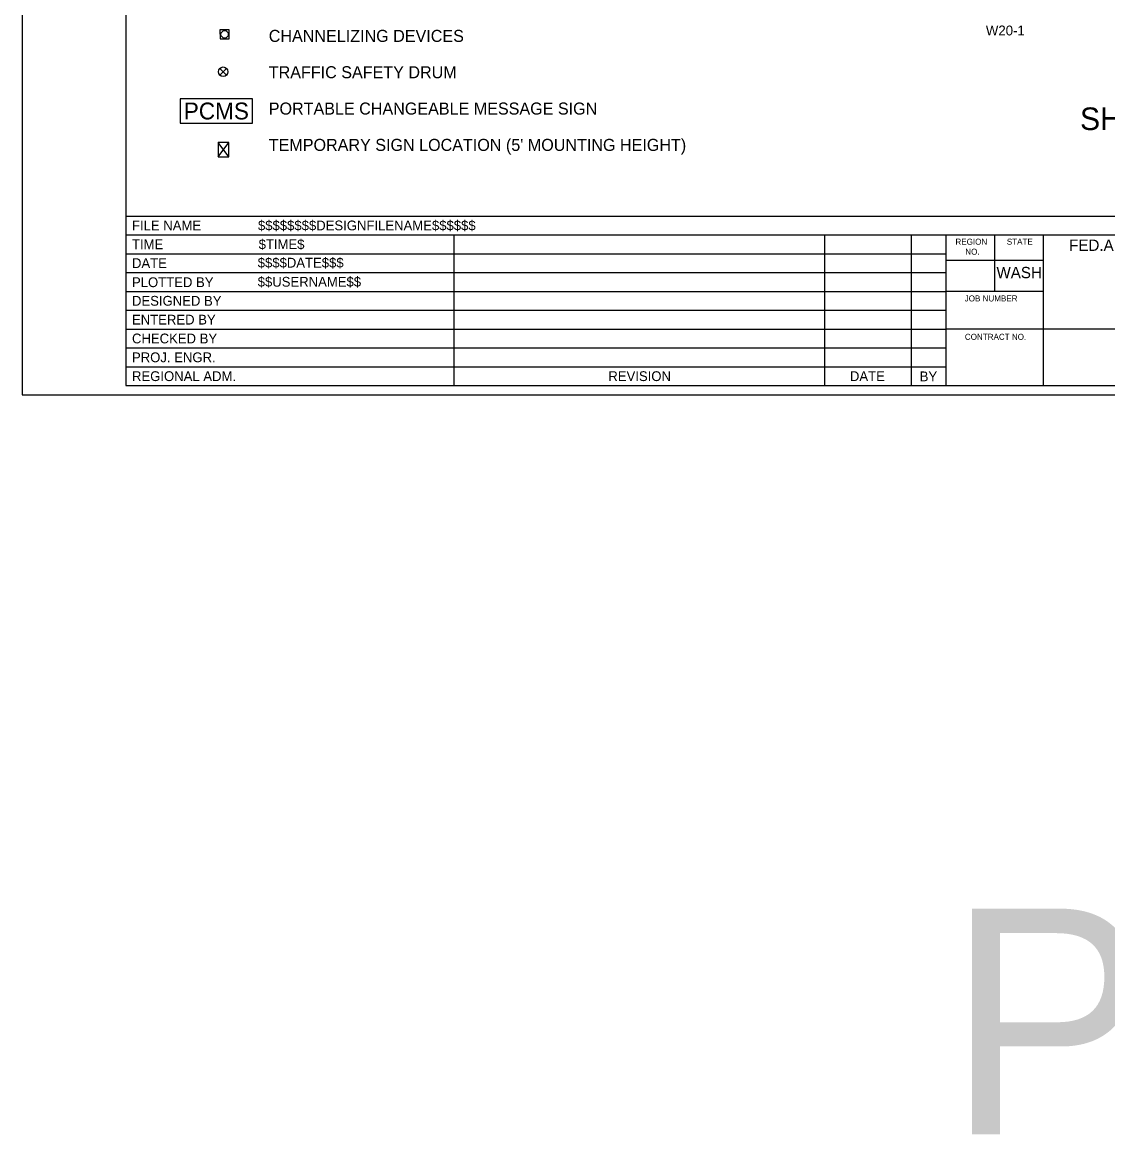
# Model space of a CAD drawing. Extents: x 99988 to 100172, y 99995 to 100047.
# Drawn here: x 99999.31 to 100006.52, y 99995.01 to 100002.41 of the extents above; entities that cross this region are included whole.
import ezdxf

# ---------------------------------------------------------------- set-up
doc = ezdxf.new("R2010")
doc.units = 0
for name, color, linetype in [('Default', 7, 'Continuous'), ('SH_DE_DetailBody1Text', 7, 'Continuous'), ('SH_DE_DetailHeading1Text', 7, 'Continuous'), ('SH_GI_PlotLimits', 7, 'Continuous'), ('SH_GI_SheetBorder', 7, 'Continuous'), ('SH_GI_SheetLocationText', 7, 'Continuous'), ('SH_GI_SheetTextInCells', 7, 'Continuous'), ('SH_GI_TitleBlockText', 7, 'Continuous'), ('TR_SN_WarningSigns', 7, 'Continuous'), ('TR_WZ_PortableChangeMessageSign', 7, 'Continuous'), ('TR_WZ_TrafficSafetyCone', 7, 'Continuous')]:
    doc.layers.add(name, color=color, linetype=linetype)

msp = doc.modelspace()

# ---------------------------------------------------------------- linework, layer by layer
at = {"layer": 'Default'}
for p, q in [((100000.6691, 100002.0611), (100000.6239, 100002.1064)), ((100000.6691, 100002.1064), (100000.6239, 100002.0611)), ((100000.6136, 100001.5195), (100000.6852, 100001.615)), ((100000.6852, 100001.5195), (100000.6136, 100001.615)), ((100000.6493, 100001.5671), (100000.6493, 100001.5671)), ((100000.6494, 100001.5673), (100000.6494, 100001.5673))]:
    msp.add_line(p, q, dxfattribs=at)
msp.add_lwpolyline([(100000.6136, 100001.5195), (100000.6852, 100001.5195), (100000.6852, 100001.615), (100000.6136, 100001.615)], close=True, dxfattribs=at)
msp.add_circle((100000.6465, 100002.0838), 0.032, dxfattribs=at)
at = {"layer": 'SH_GI_PlotLimits'}
msp.add_lwpolyline([(99999.3125, 99999.9375), (100015.8125, 99999.9375), (100015.8125, 100010.4375), (99999.3125, 100010.4375)], close=True, dxfattribs=at)
at = {"layer": 'SH_GI_SheetBorder'}
for p, q in [((100000, 100010.375), (100000, 100000)), ((100000, 100001.1259), (100015.75, 100001.1259)), ((100000, 100001.0008), (100007.4566, 100001.0008)), ((100002.179, 100001.0008), (100002.179, 100000)), ((100004.641, 100001.0008), (100004.641, 100000)), ((100005.2164, 100001.0008), (100005.2164, 100000)), ((100005.4451, 100001.0008), (100005.4451, 100000)), ((100005.7719, 100000.6255), (100005.7719, 100001.0008)), ((100006.0956, 100000), (100006.0956, 100001.0008)), ((100000, 100000.8757), (100002.1821, 100000.8757)), ((100002.1821, 100000.8757), (100005.4466, 100000.8757)), ((100006.0958, 100000.831), (100005.4466, 100000.831)), ((100000, 100000.7506), (100002.1821, 100000.7506)), ((100002.1821, 100000.7506), (100005.4466, 100000.7506)), ((100000, 100000.6255), (100005.4466, 100000.6255)), ((100006.0958, 100000.6255), (100005.4466, 100000.6255)), ((100000, 100000.5004), (100005.4466, 100000.5004)), ((100000, 100000.3753), (100005.4466, 100000.3753)), ((100007.4566, 100000.3753), (100005.4466, 100000.3753)), ((100000, 100000.2502), (100005.4466, 100000.2502)), ((100000, 100000.1251), (100005.4466, 100000.1251)), ((100000, 100000), (100015.75, 100000))]:
    msp.add_line(p, q, dxfattribs=at)
at = {"layer": 'TR_WZ_PortableChangeMessageSign'}
msp.add_lwpolyline([(100000.3604, 100001.7434), (100000.8404, 100001.7434), (100000.8404, 100001.9034), (100000.3604, 100001.9034)], close=True, dxfattribs=at)
at = {"layer": 'TR_WZ_TrafficSafetyCone'}
msp.add_lwpolyline([(100000.6862, 100002.3634), (100000.6254, 100002.3623), (100000.6265, 100002.3016), (100000.6872, 100002.3027)], close=True, dxfattribs=at)
msp.add_circle((100000.6563, 100002.3325), 0.0244, dxfattribs=at)

# ---------------------------------------------------------------- texts
at = {"layer": 'SH_DE_DetailBody1Text'}
for s, p in [('CHANNELIZING DEVICES', (100000.9494, 100002.2822)), ('TRAFFIC SAFETY DRUM', (100000.9494, 100002.0409)), ('PORTABLE CHANGEABLE MESSAGE SIGN', (100000.9494, 100001.7996)), ("TEMPORARY SIGN LOCATION (5' MOUNTING HEIGHT)", (100000.9494, 100001.5583))]:
    msp.add_text(s, height=0.08, dxfattribs=at).set_placement(p)
at = {"layer": 'SH_DE_DetailHeading1Text'}
msp.add_text(' SHORT TERM RAMP CLOSURES', height=0.15, dxfattribs=at).set_placement((100006.2813, 100001.6968))
at = {"layer": 'SH_GI_SheetLocationText'}
msp.add_text('Plot 1', height=1.5, dxfattribs=at).set_placement((100005.4547, 99995.0267))
at = {"layer": 'SH_GI_SheetTextInCells'}
for s, height, p in [('FILE NAME', 0.06505, (100000.041, 100001.0308)), ('TIME', 0.06505, (100000.041, 100000.9057)), ('REGION', 0.04003, (100005.5099, 100000.9352)), ('STATE', 0.04003, (100005.8511, 100000.9357)), ('FED.AID PROJ.NO.', 0.07506, (100006.2652, 100000.8945)), ('NO.', 0.04003, (100005.5752, 100000.869)), ('DATE', 0.06505, (100000.041, 100000.7806)), ('PLOTTED BY', 0.06505, (100000.041, 100000.6538)), ('WASH', 0.07506, (100005.7826, 100000.7131)), ('DESIGNED BY', 0.065052, (100000.041, 100000.5304)), ('JOB NUMBER', 0.04003, (100005.5712, 100000.5587)), ('ENTERED BY', 0.06505, (100000.041, 100000.4053)), ('CHECKED BY', 0.06505, (100000.041, 100000.2802)), ('CONTRACT NO.', 0.040032, (100005.5725, 100000.3037)), ('PROJ. ENGR.', 0.065052, (100000.041, 100000.1551)), ('REGIONAL ADM.', 0.065052, (100000.041, 100000.03)), ('REVISION', 0.06505, (100003.2048, 100000.03)), ('DATE', 0.06505, (100004.8091, 100000.03)), ('BY', 0.06505, (100005.2725, 100000.0285))]:
    msp.add_text(s, height=height, dxfattribs=at).set_placement(p)
at = {"layer": 'SH_GI_TitleBlockText'}
for s, height, p in [('$$$$$$$$DESIGNFILENAME$$$$$$', 0.065052, (100000.8775, 100001.0308)), ('$TIME$', 0.06505, (100000.882, 100000.9059)), ('$$$$DATE$$$', 0.065052, (100000.8759, 100000.7835)), ('$$USERNAME$$', 0.065052, (100000.8759, 100000.6567))]:
    msp.add_text(s, height=height, dxfattribs=at).set_placement(p)
at = {"layer": 'TR_SN_WarningSigns'}
msp.add_text('W20-1', height=0.06563, dxfattribs=at).set_placement((100005.712, 100002.3252))
at = {"layer": 'TR_WZ_PortableChangeMessageSign'}
msp.add_text('PCMS', height=0.112, rotation=360, dxfattribs=at).set_placement((100000.3849, 100001.7674))

doc.saveas('drawing.dxf')
